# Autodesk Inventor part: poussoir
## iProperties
Created: 2011-09
Part Number: poussoir
Document SubType Name: Modeling
Designer: Dominique
Author: Dominique
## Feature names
1. Extrusion1
2. Extrusion2
3. Extrusion3
4. Chanfrein1 [Chamfer]
5. Extrusion4
6. Perçage1 [Hole]
